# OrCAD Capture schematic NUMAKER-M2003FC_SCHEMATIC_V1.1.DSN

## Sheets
1 Nu-Link2-Me (TypeC): size A3; title: Nu-Link2-Me; rev: 1.0; company: CMHuang; note: Nu-Link2-Me
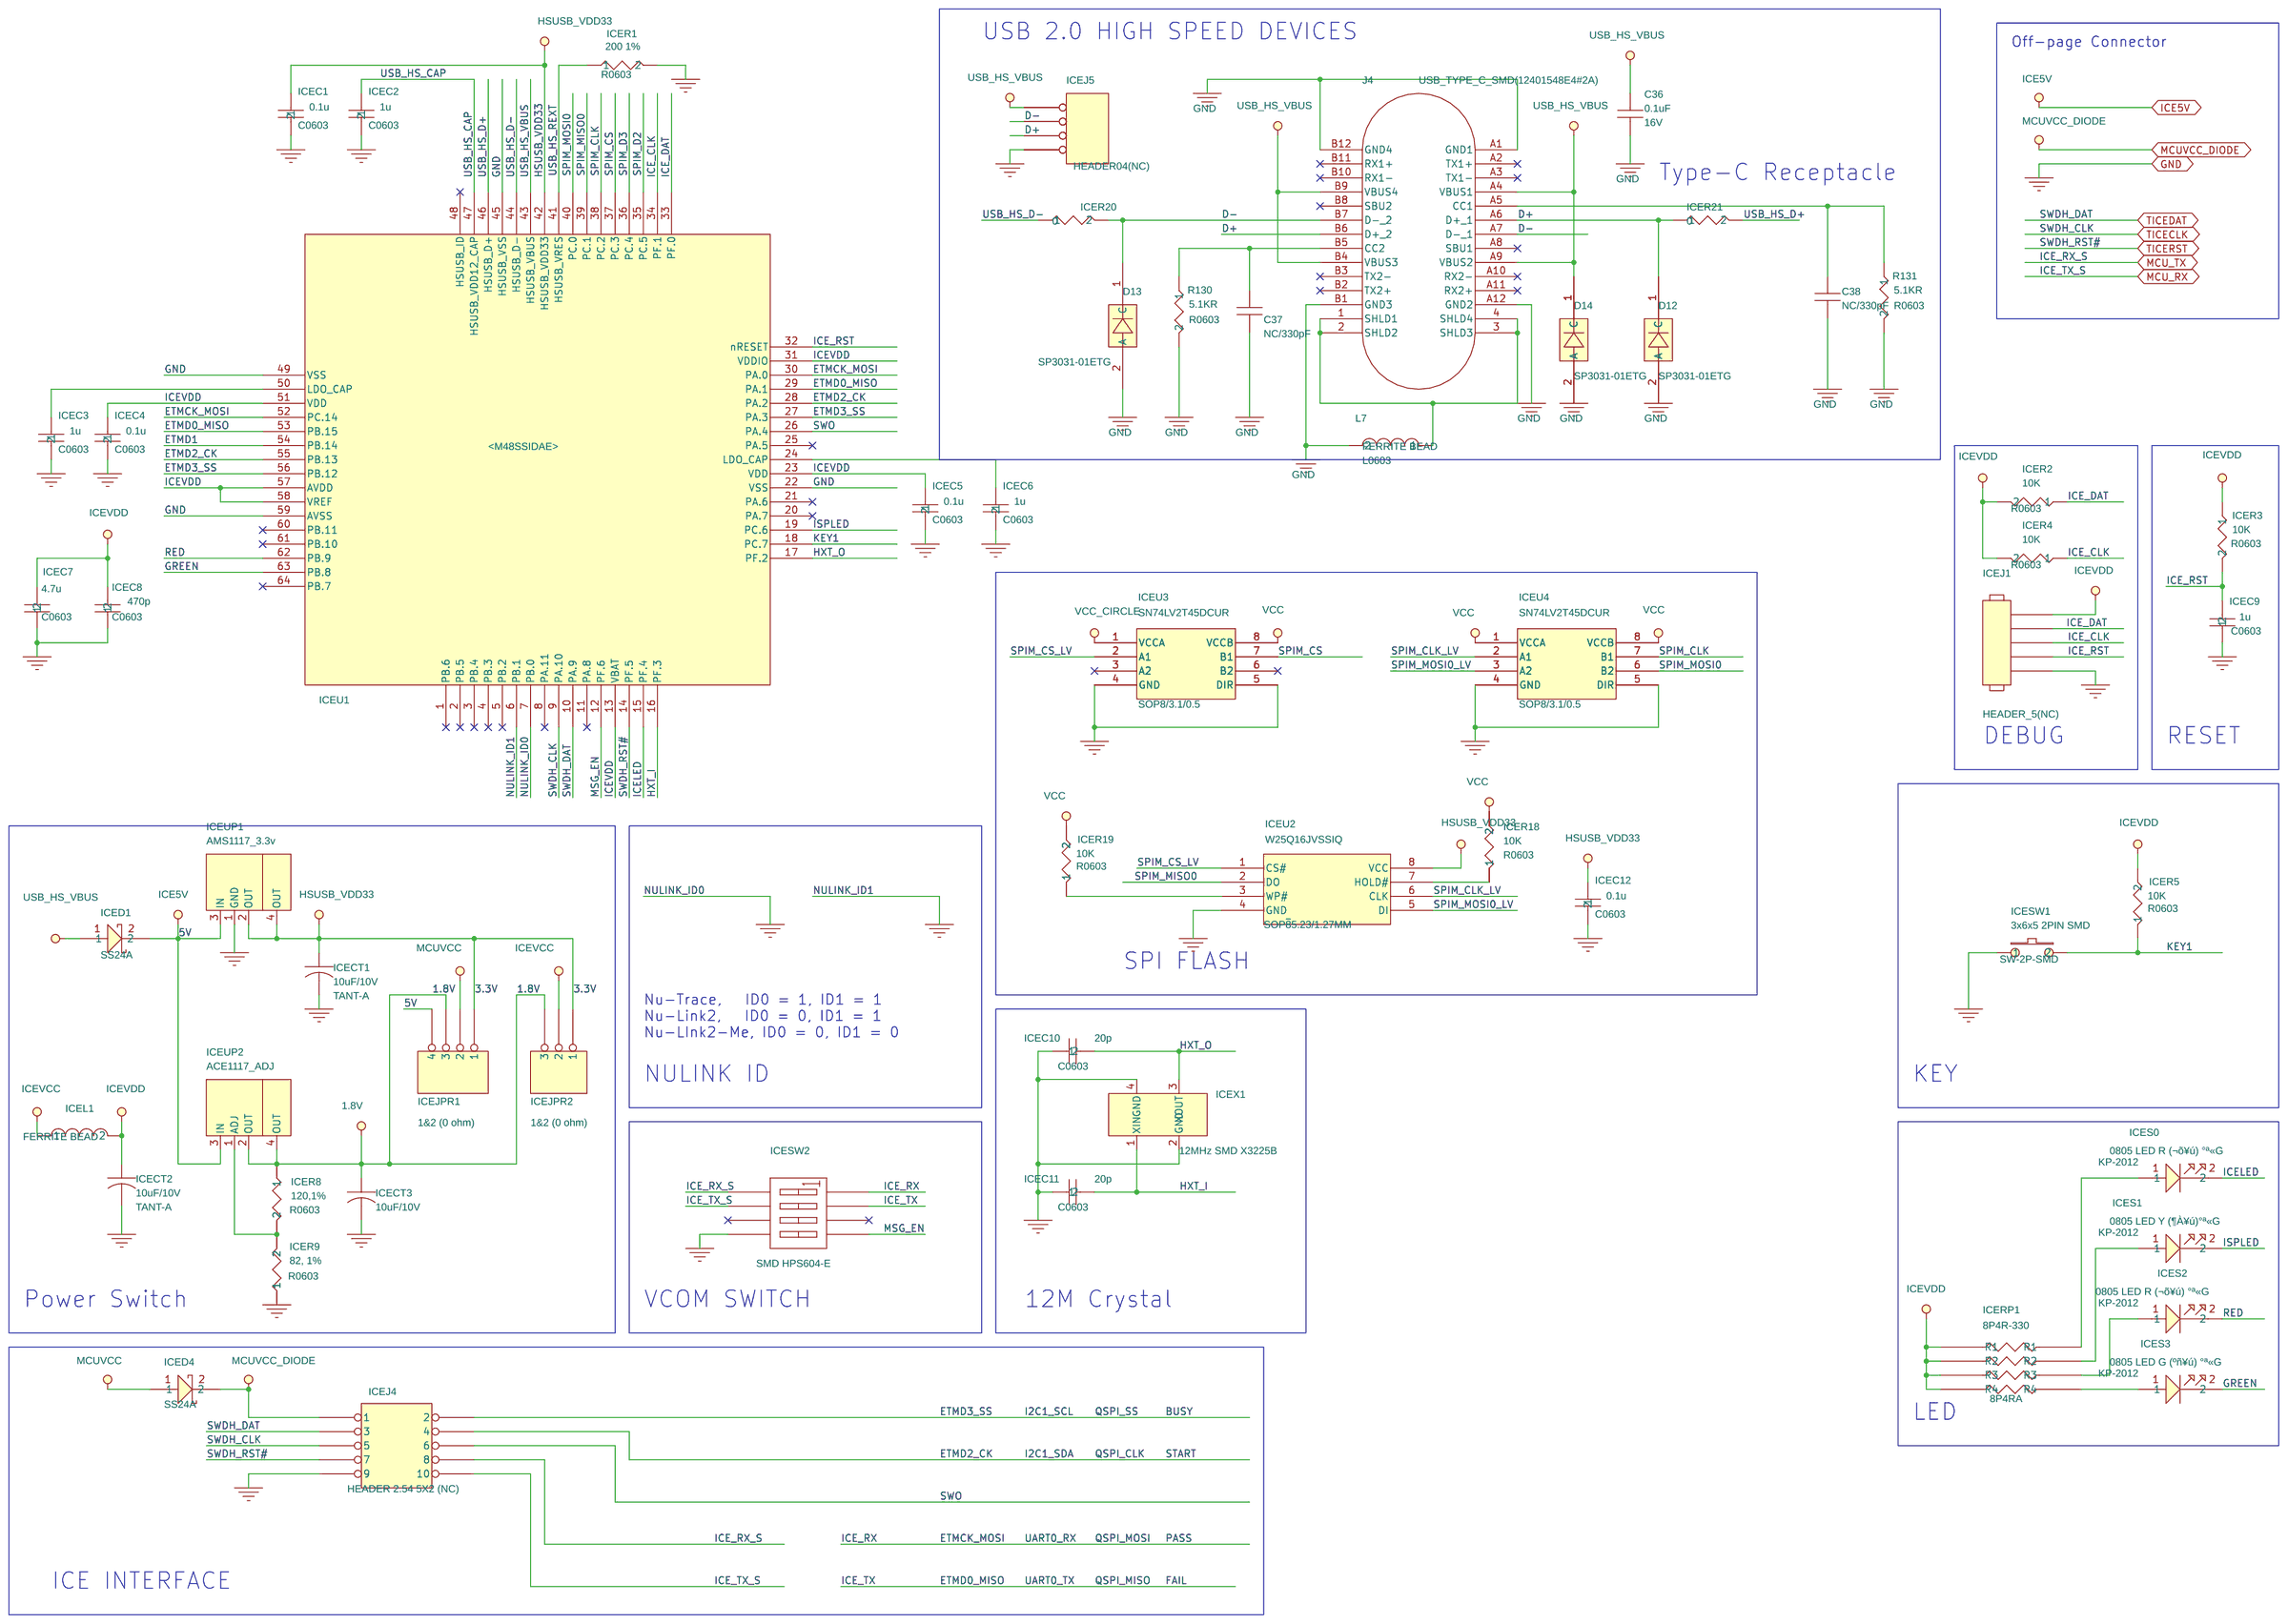
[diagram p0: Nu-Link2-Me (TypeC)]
2 M2003FC1AE: size Custom; title: M2003FC1AE; rev: v1.1; note: NuMaker-M2003FC
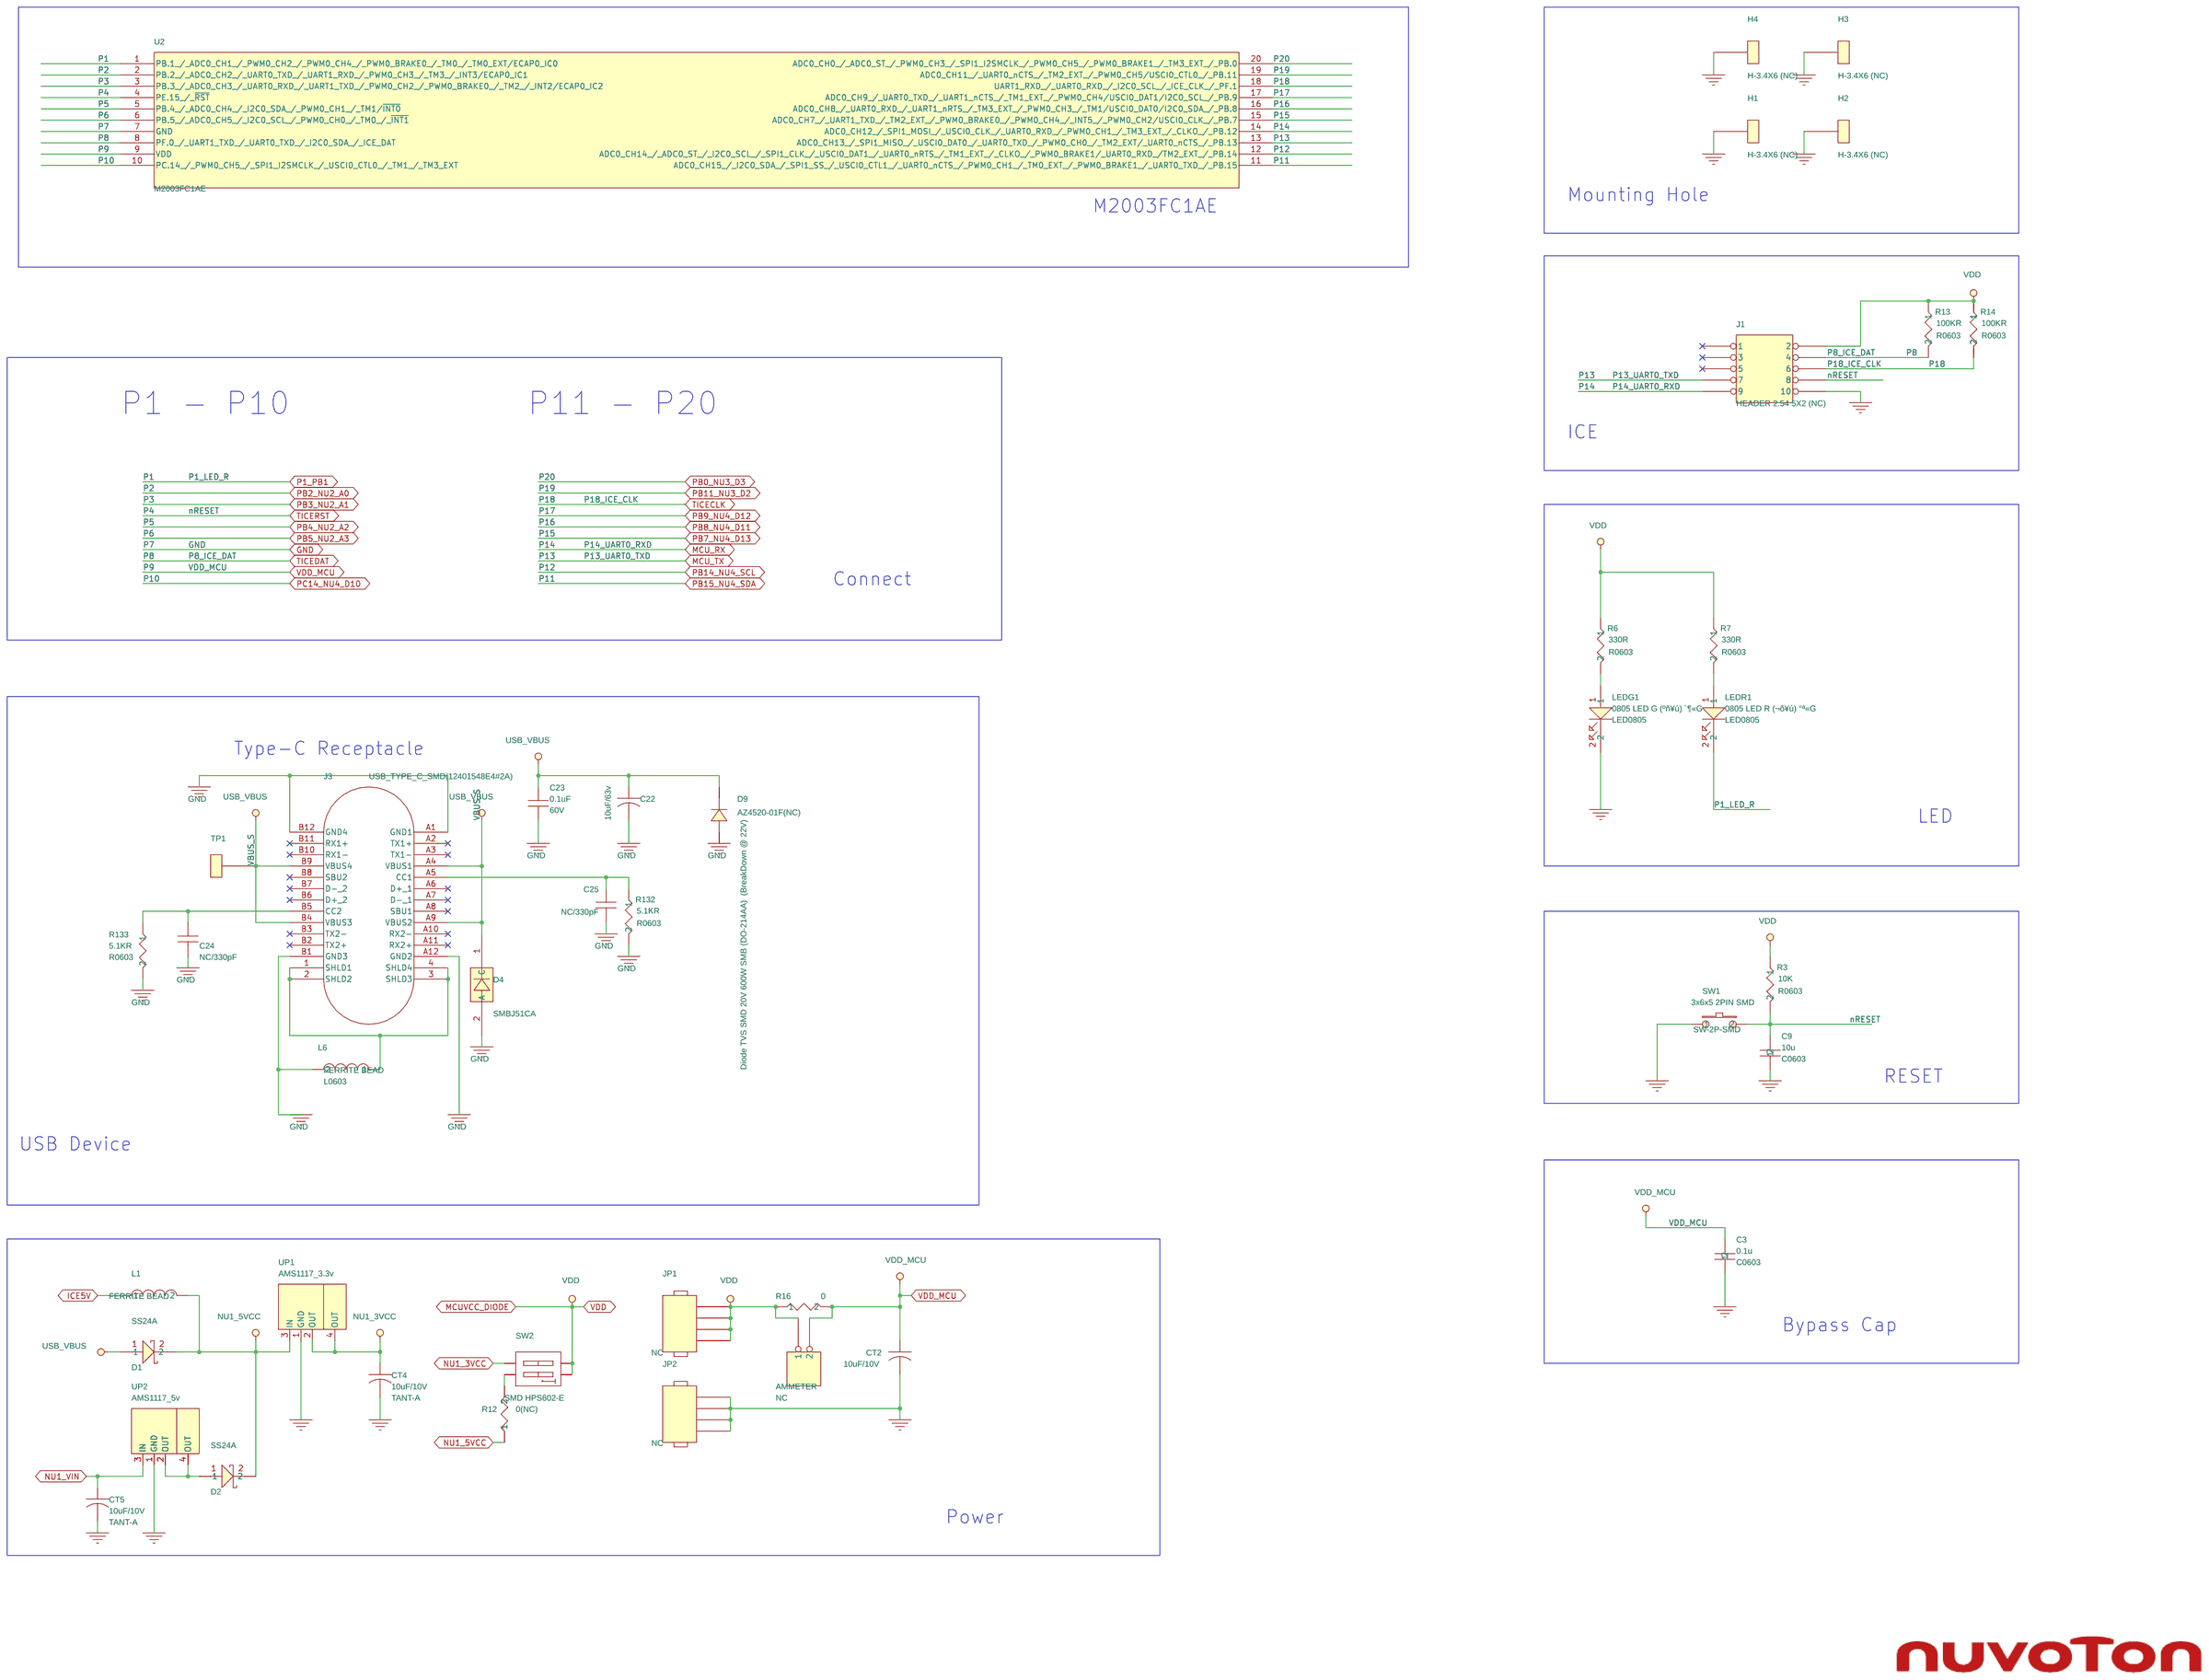
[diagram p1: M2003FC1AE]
3 Ext. Connector: size Custom; title: Ext. Connector; rev: v1.1; note: NuMaker-M2003FC
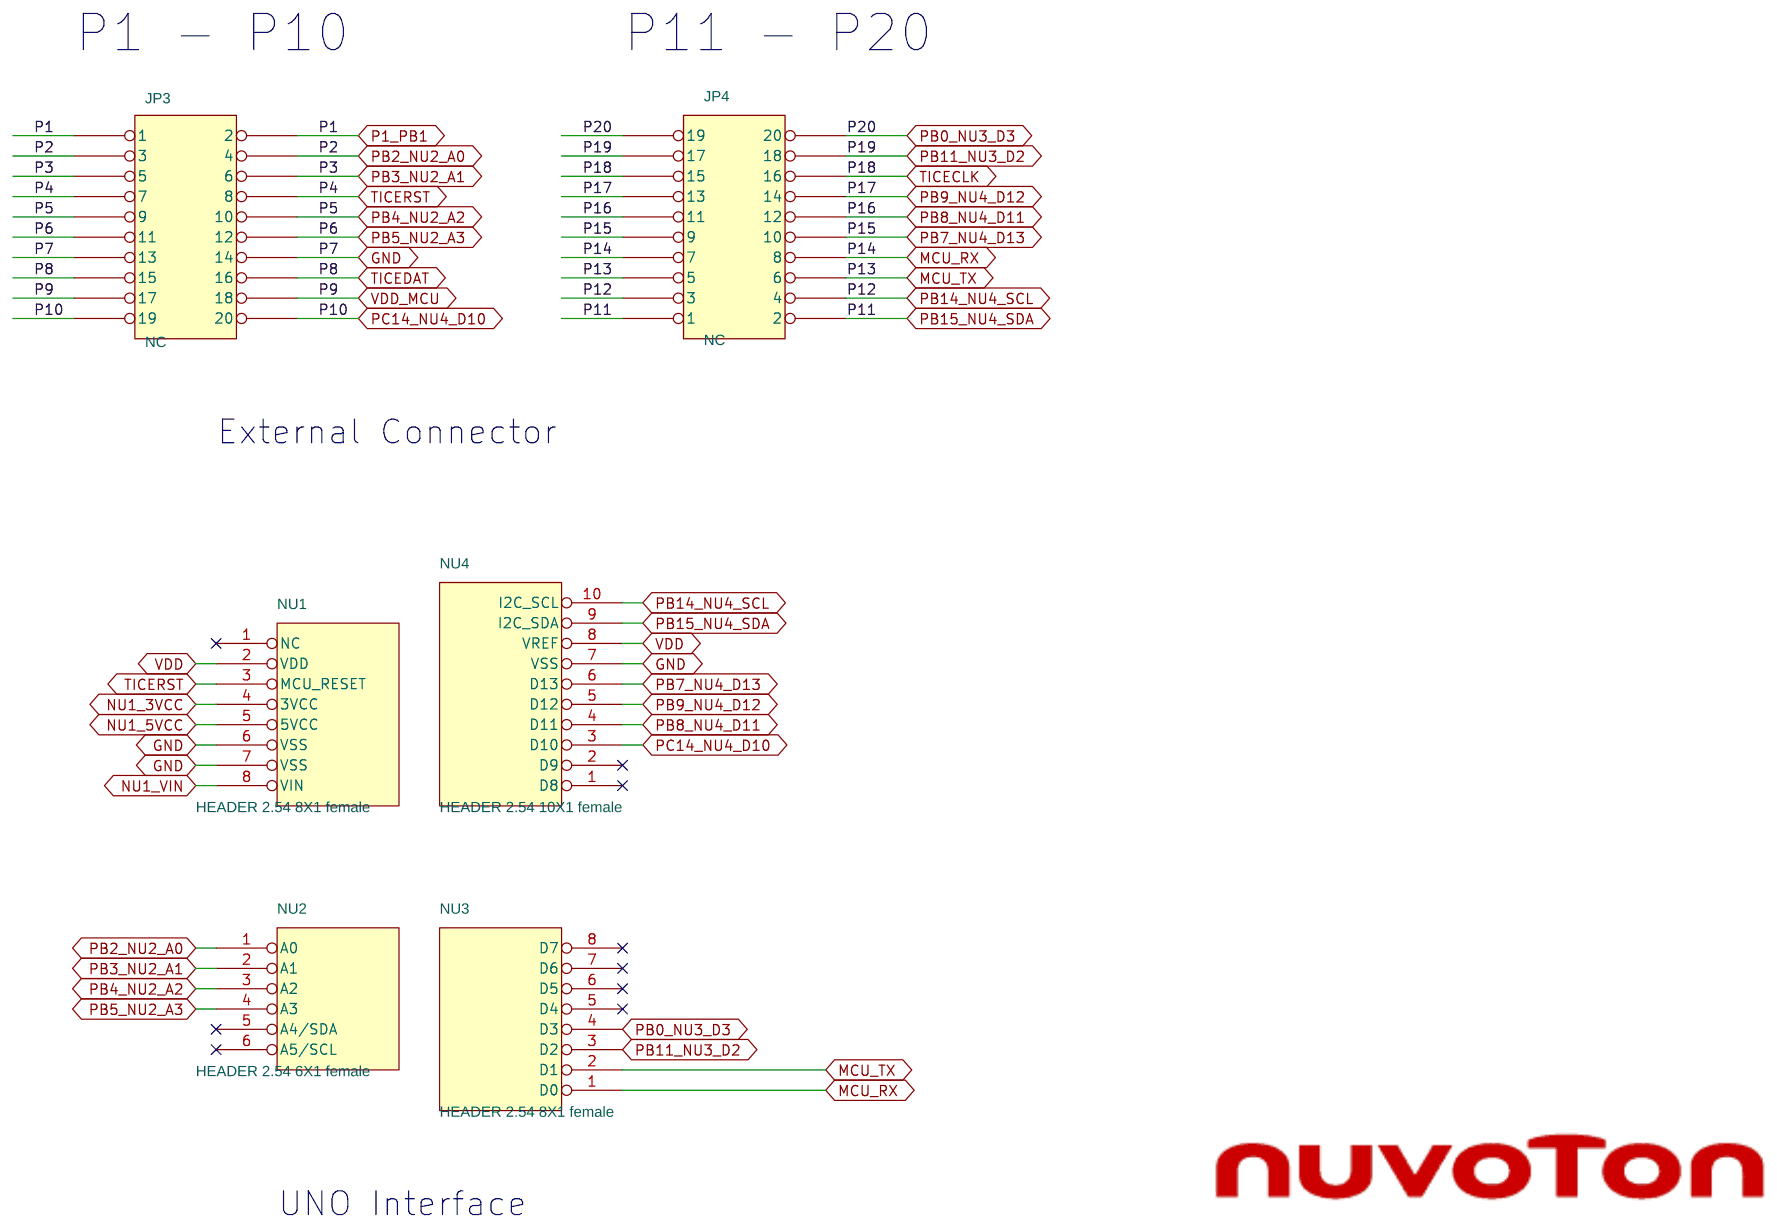
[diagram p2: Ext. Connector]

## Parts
sheet Ext. Connector
JP3  NC  [HEADER10x2]
JP4  NC  [HEADER10x2]
NU1  HEADER 2.54 8X1 female  [SIP-8P]
NU2  HEADER 2.54 6X1 female  [SIP-6P]
NU3  HEADER 2.54 8X1 female  [SIP-8P]
NU4  HEADER 2.54 10X1 female  [SIP-10P]
sheet M2003FC1AE
AMMETER  NC  [HEADER2X1]
C3  0.1u  [C0603]
C9  10u  [C0603]
C22  10uF/63v  [CES/6.3D/P]
C23  0.1uF  [C0603]
C24  NC/330pF  [C0603]
C25  NC/330pF  [C0603]
CT2  10uF/10V  [TANT-A]
CT4  10uF/10V  [TANT-A]
CT5  10uF/10V  [TANT-A]
D1  SS24A  [RB060L]
D2  SS24A  [RB060L]
D4  SMBJ51CA  [DO-214AA]
D9  AZ4520-01F(NC)  [DO-214AA/SMB]
H1  H-3.4X6 (NC)  [H-3.4X6]
H2  H-3.4X6 (NC)  [H-3.4X6]
H3  H-3.4X6 (NC)  [H-3.4X6]
H4  H-3.4X6 (NC)  [H-3.4X6]
J1  HEADER 2.54 5X2 (NC)  [HEADER5X2]
J3  USB_TYPE_C_SMD(12401548E4#2A)  [400981]
JP1  NC  [header1x4]
JP2  NC  [header1x4]
L1  FERRITE BEAD  [L0603]
L6  FERRITE BEAD  [L0603]
LEDG1  0805 LED G (ºñ¥ú) ´¶«G  [LED0805]
LEDR1  0805 LED R (¬õ¥ú) °ª«G  [LED0805]
R3  10K  [R0603]
R6  330R  [R0603]
R7  330R  [R0603]
R12  0(NC)  [R0603]
R13  100KR  [R0603]
R14  100KR  [R0603]
R16  0  [R0603]
R132  5.1KR  [R0603]
R133  5.1KR  [R0603]
SW1  3x6x5 2PIN SMD  [SW-2P-SMD]
SW2  SMD HPS602-E  [SW1X2]
TP1  TEST_POINT
U2  M2003FC1AE  [TSSOP20]
UP1  AMS1117_3.3v  [SOT-223-1]
UP2  AMS1117_5v  [SOT-223-1]
sheet Nu-Link2-Me (TypeC)
C36  0.1uF  [C0603]
C37  NC/330pF  [C0603]
C38  NC/330pF  [C0603]
D12  SP3031-01ETG  [SOD882]
D13  SP3031-01ETG  [SOD882]
D14  SP3031-01ETG  [SOD882]
ICEC1  0.1u  [C0603]
ICEC2  1u  [C0603]
ICEC3  1u  [C0603]
ICEC4  0.1u  [C0603]
ICEC5  0.1u  [C0603]
ICEC6  1u  [C0603]
ICEC7  4.7u  [C0603]
ICEC8  470p  [C0603]
ICEC9  1u  [C0603]
ICEC10  20p  [C0603]
ICEC11  20p  [C0603]
ICEC12  0.1u  [C0603]
ICECT1  10uF/10V  [TANT-A]
ICECT2  10uF/10V  [TANT-A]
ICECT3  10uF/10V  [TANT-A]
ICED1  SS24A  [RB060L]
ICED4  SS24A  [RB060L]
ICEJ1  HEADER_5(NC)  [HEADER5X1]
ICEJ4  HEADER 2.54 5X2 (NC)  [HEADER5X2]
ICEJ5  HEADER04(NC)  [HEADER04]
ICEJPR1  1&2 (0 ohm)  [R0603X3]
ICEJPR2  1&2 (0 ohm)  [R0603X2]
ICEL1  FERRITE BEAD  [L0603]
ICER1  200 1%  [R0603]
ICER2  10K  [R0603]
ICER3  10K  [R0603]
ICER4  10K  [R0603]
ICER5  10K  [R0603]
ICER8  120,1%  [R0603]
ICER9  82, 1%  [R0603]
ICER18  10K  [R0603]
ICER19  10K  [R0603]
ICER20  0  [R0603]
ICER21  0  [R0603]
ICERP1  8P4R-330  [8P4RA]
ICES0  0805 LED R (¬õ¥ú) °ª«G  [KP-2012]
ICES1  0805 LED Y (¶À¥ú)°ª«G  [KP-2012]
ICES2  0805 LED R (¬õ¥ú) °ª«G  [KP-2012]
ICES3  0805 LED G (ºñ¥ú) °ª«G  [KP-2012]
ICESW1  3x6x5 2PIN SMD  [SW-2P-SMD]
ICESW2  SMD HPS604-E  [SW1X4]
ICEU1  M48SSIDAE  [LQFP64_7x7_M48SSIDAE]
ICEU2  W25Q16JVSSIQ  [SOP8\5.23/1.27MM]
ICEU3  SN74LV2T45DCUR  [SOP8/3.1/0.5]
ICEU4  SN74LV2T45DCUR  [SOP8/3.1/0.5]
ICEUP1  AMS1117_3.3v  [SOT-223-1]
ICEUP2  ACE1117_ADJ  [SOT-223-1]
ICEX1  12MHz SMD X3225B  [CRYSTAL_SMD]
J4  USB_TYPE_C_SMD(12401548E4#2A)  [400981]
L7  FERRITE BEAD  [L0603]
R130  5.1KR  [R0603]
R131  5.1KR  [R0603]

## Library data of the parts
JP3 = HEADER_10X2
JP4 = HEADER_10X2_1
NU1 = POWER_CONNECT_0
NU2 = ADC_CONNECT_0
NU3 = PWM0_CONNECT_0
NU4 = PWM1_CONNECT_1
AMMETER = HEADER_2
C3 ICEC4 = CAP-C: Package: 0603; element_no: C0004
C9 = CAP-C_1: Package: 0603; element_no: C0006
C22 CT2 CT4 CT5 ICECT1-ICECT3 = C_10uF_10V
C23 = CAPACITOR_NP: CAP CER X7R SMD 0.1uF 10% 50V 0603; Mount: M; Part Number: 880600286; Part Type: Capacitor\Ceramic; Raing/Power: 60V; Tolerance: 10%
C24 C25 C37 C38 = CAPACITOR_NP: CAP CER NPO SMD 330pF 5% 50V 0603; Mount: M; Part Number: 880600252; Part Type: Capacitor\Ceramic; Raing/Power: 50V; Tolerance: 5%
D1 ICED4 = D_SS24A_1
D2 ICED1 = D_SS24A
D4 = Schottky_Barrier_Diode_0: Diode SMD Schottky Barrier 30V; Mount: M; Part Number: 880900908
D9 = DIODE21: Diode TVS SMD 20V 600W SMB (DO-214AA)  (BreakDown @ 22V); Mount: M; Part Number: 880900866; Part Type: Diode
H1-H4 TP1 = TEST_POINT
ICEJ4 J1 = HEADER_5X2
J3 J4 = USB_TYPE_C_2: CON USB 3.0 Type C receptical SMD & TH; Mount: M; Part Number: 880400981; Part Type: Connector
JP1 JP2 = HEADER_4
ICEL1 L1 = FERRITE_BEAD_1
L6 L7 = FERRITE_BEAD
LEDG1 = LED_0_1: Package: KP-2012; Vendor: Kingbright
LEDR1 = LED_0: Package: KP-2012; Vendor: Kingbright
ICER5 R3 = R_0_2: Package: 0603
ICER2 R6 = R_0_5: Package: 0603
ICER8 R7 = R_0: Package: 0603
R12 = R_0_6
ICER18 R13 = R_0_4: Package: 0603
ICER1 R14 = R_0_7: Package: 0603
R16 = R_0_8
ICER4 R132 = R_0_3: Package: 0603
ICER3 R133 = R_0_1: Package: 0603
ICESW1 SW1 = SW_PUSHBUTTON_0
SW2 = SW_DIP-4_2
U2 = SA8191_LQFP_48L_2
ICEUP1 UP1 UP2 = TO-247_Regulator_10
C36 = CAPACITOR_NP: CAP CER X7R SMD 0.1uF 10% 50V 0603; Mount: M; Part Number: 880600286; Part Type: Capacitor\Ceramic; Raing/Power: 16V; Tolerance: 10%
D12-D14 = Schottky_Barrier_Diode_1: Diode SMD Schottky Barrier 30V; Mount: M; Part Number: 880900908
ICEC1 = CAP-C_10: Package: 0603; element_no: C0004
ICEC2 = CAP-C_9: Package: 0603; element_no: C0006
ICEC3 = CAP-C_7: Package: 0603; element_no: C0006
ICEC5 = CAP-C_2: Package: 0603; element_no: C0004
ICEC6 = CAP-C_5: Package: 0603; element_no: C0006
ICEC7 = CAP-C_3: Package: 0603
ICEC8 = CAP-C_8: Package: 0603
ICEC9 = CAP-C_6: Package: 0603; element_no: C0006
ICEC10 = CAP-C_11: Package: 0603
ICEC11 = CAP-C_4: Package: 0603
ICEC12 = CAP-C_1: Package: 0603; element_no: C0004
ICEJ1 = HEADER_5_v2
ICEJ5 = HEADER_4_v2
ICEJPR1 = HEADER_3_0
ICEJPR2 = HEADER_3
ICER9 = R_0_8: Package: 0603
ICER19 = R_0_10: Package: 0603
ICER20 = R_33
ICER21 = R_33_1
ICERP1 = R-PACK8_0
ICES0 = LED_0_2: Vendor: Kingbright
ICES1 = LED_0_3: Vendor: Kingbright
ICES2 = LED_0_1: Vendor: Kingbright
ICES3 = LED_0: Vendor: Kingbright
ICESW2 = SW_DIP-4_SM
ICEU1 = M487SIDAE_0: M487SIDAE: <M48SSIDAE>
ICEU2 = W25P10_20_40_SOIC_0: Package: SOP8; Vendor: WINBOND
ICEU3 ICEU4 = SN74LV2T45
ICEUP2 = TO-247_Regulator_0
ICEX1 = Crystal_SMD_1
R130 = R_0_6: Package: 0603
R131 = R_0_9: Package: 0603

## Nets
1.8V: ICECT3.1 ICEJPR1.3 ICEJPR2.3 ICER8.1 ICEUP2.2(OUT) ICEUP2.4(OUT)
3.3V: ICEC1.1 ICEC12.1 ICECT1.1 ICEJPR1.1 ICEJPR2.1 ICER18.2 ICER19.2 ICEU1.42(HSUSB_VDD33) ICEU2.8(VCC) ICEU3.1(VCCA) ICEU4.1(VCCA) ICEUP1.2(OUT) ICEUP1.4(OUT)
GND: C3.1 C9.1 C22.2 C23.2 C24.2 C25.2 C36.2 C37.2 C38.2 CT2.2 CT4.2 CT5.2 D4.2(A) D9.2(A) D12.2(A) D13.2(A) D14.2(A) H1.1 H2.1 H3.1 H4.1 ICEC1.2 ICEC2.2 ICEC3.2 ICEC4.2 ICEC5.2 ICEC6.2 ICEC7.1 ICEC8.1 ICEC9.1 ICEC10.1 ICEC11.1 ICEC12.2 ICECT1.2 ICECT2.2 ICECT3.2 ICEJ1.5 ICEJ4.9 ICEJ5.4 ICER1.2 ICER9.1 ICESW1.1 ICESW2.4(A4) ICEU1.6(PB.1) ICEU1.7(PB.0) ICEU1.22(VSS) ICEU1.45(HSUSB_VSS) ICEU1.49(VSS) ICEU1.59(AVSS) ICEU2.4(GND) ICEU3.4(GND) ICEU3.5(DIR) ICEU4.4(GND) ICEU4.5(DIR) ICEUP1.1(GND) ICEX1.2(GND) ICEX1.4(GND) J1.10 J3.A1(GND1) J3.A12(GND2) J3.B1(GND3) J3.B12(GND4) J4.A1(GND1) J4.A12(GND2) J4.B1(GND3) J4.B12(GND4) JP2.1 JP2.2 JP2.3 JP2.4 JP3.13 JP3.14 L6.2 L7.2 LEDG1.2 NU1.6(VSS) NU1.7(VSS) NU4.7(VSS) R130.2 R131.2 R132.2 R133.2 SW1.1 U2.7(GND) UP1.1(GND) UP2.1(GND)
VDD: AMMETER.1 ICED4.2 ICEJ4.1 J1.2 JP1.1 JP1.2 JP1.3 JP1.4 NU1.2(VDD) NU4.8(VREF) R3.1 R6.1 R7.1 R13.1 R14.1 R16.1 SW2.3(B1) SW2.4(B2)
VDD_MCU: AMMETER.2 C3.2 CT2.1 JP3.17 JP3.18 R16.2 U2.9(VDD)
BUSY: ICEJ4.2 ICEU1.27(PA.3) ICEU1.56(PB.12)
D+: D12.1(C) ICEJ5.3 ICER21.1 J4.A6(D+_1) J4.B6(D+_2)
D-: D13.1(C) ICEJ5.2 ICER20.2 J4.A7(D-_1) J4.B7(D-_2)
ETMD1: ICEU1.54(PB.14)
ETMD2_CK: ICEJ4.4 ICEU1.28(PA.2) ICEU1.55(PB.13)
GREEN: ICES3.2 ICEU1.63(PB.8)
HXT_I: ICEC11.2 ICEU1.16(PF.3) ICEX1.1(XIN)
HXT_O: ICEC10.2 ICEU1.17(PF.2) ICEX1.3(XOUT)
ICE5V: ICED1.2 ICEJPR1.4 ICEUP1.3(IN) ICEUP2.3(IN) L1.1
ICE_CLK: ICEJ1.3 ICER4.1 ICEU1.34(PF.1)
ICE_DAT: ICEJ1.2 ICER2.1 ICEU1.33(PF.0)
ICE_RST: ICEC9.2 ICEJ1.4 ICER3.2 ICEU1.32(nRESET)
ICE_RX: ICESW2.8(B1) ICEU1.30(PA.0) ICEU1.52(PC.14)
ICE_TX: ICESW2.7(B2) ICEU1.29(PA.1) ICEU1.53(PB.15)
ICELED: ICES0.2 ICEU1.15(PF.4)
ICEVCC: ICEJPR2.2 ICEL1.1
ICEVDD: ICEC4.1 ICEC5.1 ICEC7.2 ICEC8.2 ICECT2.1 ICEJ1.1 ICEL1.2 ICER2.2 ICER3.1 ICER4.2 ICER5.2 ICERP1.1(R1) ICERP1.3(R2) ICERP1.5(R3) ICERP1.7(R4) ICEU1.13(VBAT) ICEU1.23(VDD) ICEU1.31(VDDIO) ICEU1.51(VDD) ICEU1.57(AVDD) ICEU1.58(VREF) ICEU3.8(VCCB) ICEU4.8(VCCB)
ISPLED: ICES1.2 ICEU1.19(PC.6)
KEY1: ICER5.1 ICESW1.2 ICEU1.18(PC.7)
MCU_RX: ICEJ4.10 ICESW2.2(A2) J1.9 JP4.7 JP4.8 NU3.1(D0) U2.14(ADC0_CH12_/_SPI1_MOSI_/_USCI0_CLK_/_UART0_RXD_/_PWM0_CH1_/_TM3_EXT_/_CLKO_/_PB.12)
MCU_TX: ICEJ4.8 ICESW2.1(A1) J1.7 JP4.5 JP4.6 NU3.2(D1) U2.13(ADC0_CH13_/_SPI1_MISO_/_USCI0_DAT0_/_UART0_TXD_/_PWM0_CH0_/_TM2_EXT/_UART0_nCTS_/_PB.13)
MCUVCC: ICED4.1 ICEJPR1.2
MSG_EN: ICESW2.5(B4) ICEU1.12(PF.6)
NU1_3VCC: CT4.1 NU1.4(3VCC) SW2.2(A2) UP1.2(OUT) UP1.4(OUT)
NU1_5VCC: D1.2 D2.2 L1.2 NU1.5(5VCC) R12.1 UP1.3(IN)
NU1_VIN: CT5.1 NU1.8(VIN) UP2.3(IN)
P1_PB1: JP3.1 JP3.2 LEDR1.2 U2.1(PB.1_/_ADC0_CH1_/_PWM0_CH2_/_PWM0_CH4_/_PWM0_BRAKE0_/_TM0_/_TM0_EXT/ECAP0_IC0)
PB0_NU3_D3: JP4.19 JP4.20 NU3.4(D3) U2.20(ADC0_CH0_/_ADC0_ST_/_PWM0_CH3_/_SPI1_I2SMCLK_/_PWM0_CH5_/_PWM0_BRAKE1_/_TM3_EXT_/_PB.0)
PB2_NU2_A0: JP3.3 JP3.4 NU2.1(A0) U2.2(PB.2_/_ADC0_CH2_/_UART0_TXD_/_UART1_RXD_/_PWM0_CH3_/_TM3_/_INT3/ECAP0_IC1)
PB3_NU2_A1: JP3.5 JP3.6 NU2.2(A1) U2.3(PB.3_/_ADC0_CH3_/_UART0_RXD_/_UART1_TXD_/_PWM0_CH2_/_PWM0_BRAKE0_/_TM2_/_INT2/ECAP0_IC2)
PB4_NU2_A2: JP3.9 JP3.10 NU2.3(A2) U2.5(PB.4_/_ADC0_CH4_/_I2C0_SDA_/_PWM0_CH1_/_TM1/~{INT0})
PB5_NU2_A3: JP3.11 JP3.12 NU2.4(A3) U2.6(PB.5_/_ADC0_CH5_/_I2C0_SCL_/_PWM0_CH0_/_TM0_/_~{INT1})
PB7_NU4_D13: JP4.9 JP4.10 NU4.6(D13) U2.15(ADC0_CH7_/_UART1_TXD_/_TM2_EXT_/_PWM0_BRAKE0_/_PWM0_CH4_/_INT5_/_PWM0_CH2/USCI0_CLK_/_PB.7)
PB8_NU4_D11: JP4.11 JP4.12 NU4.4(D11) U2.16(ADC0_CH8_/_UART0_RXD_/_UART1_nRTS_/_TM3_EXT_/_PWM0_CH3_/_TM1/USCI0_DAT0/I2C0_SDA_/_PB.8)
PB9_NU4_D12: JP4.13 JP4.14 NU4.5(D12) U2.17(ADC0_CH9_/_UART0_TXD_/_UART1_nCTS_/_TM1_EXT_/_PWM0_CH4/USCI0_DAT1/I2C0_SCL_/_PB.9)
PB11_NU3_D2: JP4.17 JP4.18 NU3.3(D2) U2.19(ADC0_CH11_/_UART0_nCTS_/_TM2_EXT_/_PWM0_CH5/USCI0_CTL0_/_PB.11)
PB14_NU4_SCL: JP4.3 JP4.4 NU4.10(I2C_SCL) U2.12(ADC0_CH14_/_ADC0_ST_/_I2C0_SCL_/_SPI1_CLK_/_USCI0_DAT1_/_UART0_nRTS_/_TM1_EXT_/_CLKO_/_PWM0_BRAKE1/_UART0_RXD_/TM2_EXT_/_PB.14)
PB15_NU4_SDA: JP4.1 JP4.2 NU4.9(I2C_SDA) U2.11(ADC0_CH15_/_I2C0_SDA_/_SPI1_SS_/_USCI0_CTL1_/_UART0_nCTS_/_PWM0_CH1_/_TM0_EXT_/_PWM0_BRAKE1_/_UART0_TXD_/_PB.15)
PC14_NU4_D10: JP3.19 JP3.20 NU4.3(D10) U2.10(PC.14_/_PWM0_CH5_/_SPI1_I2SMCLK_/_USCI0_CTL0_/_TM1_/_TM3_EXT)
RED: ICES2.2 ICEU1.62(PB.9)
SPIM_CLK: ICEU1.38(PC.2) ICEU4.7(B1)
SPIM_CLK_LV: ICEU2.6(CLK) ICEU4.2(A1)
SPIM_CS: ICEU1.37(PC.3) ICEU3.7(B1)
SPIM_CS_LV: ICEU2.1(CS#) ICEU3.2(A1)
SPIM_D2: ICEU1.35(PC.5)
SPIM_D3: ICEU1.36(PC.4)
SPIM_MISO0: ICEU1.39(PC.1) ICEU2.2(DO)
SPIM_MOSI0: ICEU1.40(PC.0) ICEU4.6(B2)
SPIM_MOSI0_LV: ICEU2.5(DI) ICEU4.3(A2)
SWO: ICEJ4.6 ICEU1.26(PA.4)
TICECLK: ICEJ4.5 ICEU1.9(PA.10) J1.6 JP4.15 JP4.16 R14.2 U2.18(UART1_RXD_/_UART0_RXD_/_I2C0_SCL_/_ICE_CLK_/_PF.1)
TICEDAT: ICEJ4.3 ICEU1.10(PA.9) J1.4 JP3.15 JP3.16 R13.2 U2.8(PF.0_/_UART1_TXD_/_UART0_TXD_/_I2C0_SDA_/_ICE_DAT)
TICERST: C9.2 ICEJ4.7 ICEU1.14(PF.5) J1.8 JP3.7 JP3.8 NU1.3(MCU_RESET) R3.2 SW1.2 U2.4(PE.15_/_~{RST})
USB_HS_CAP: ICEC2.1 ICEU1.47(HSUSB_VDD12_CAP)
USB_HS_D+: ICER21.2 ICEU1.46(HSUSB_D+)
USB_HS_D-: ICER20.1 ICEU1.44(HSUSB_D-)
USB_HS_REXT: ICER1.1 ICEU1.41(HSUSB_VRES)
USB_HS_VBUS: C36.1 D14.1(C) ICED1.1 ICEJ5.1 ICEU1.43(HSUSB_VBUS) J4.A4(VBUS1) J4.A9(VBUS2) J4.B4(VBUS3) J4.B9(VBUS4)
USB_VBUS: C22.1 C23.1 D1.1 D4.1(C) D9.1(K) J3.A4(VBUS1) J3.A9(VBUS2) J3.B4(VBUS3) J3.B9(VBUS4) TP1.1
N16825237: LEDG1.1 R6.2
N16825240: LEDR1.1 R7.2
N16840819: ICEC6.1 ICEU1.24(LDO_CAP)
N16840960: ICEC3.1 ICEU1.50(LDO_CAP)
N17019924: ICER8.2 ICER9.2 ICEUP2.1(ADJ)
N17029977: ICERP1.8(R4) ICES3.1
N17029979: ICERP1.6(R3) ICES2.1
N17030004: ICERP1.4(R2) ICES1.1
N17030010: ICERP1.2(R1) ICES0.1
N17125028: R12.2 SW2.1(A1)
N17155328: ICER18.1 ICEU2.7(HOLD#)
N17155343: ICER19.1 ICEU2.3(WP#)
N17167442: D2.1 UP2.2(OUT) UP2.4(OUT)
N17285540: C25.1 J3.A5(CC1) R132.1
N17285578: C24.1 J3.B5(CC2) R133.1
N17285609: J3.1(SHLD1) J3.2(SHLD2) J3.3(SHLD3) J3.4(SHLD4) L6.1
N17357255: C38.1 J4.A5(CC1) R131.1
N17357296: C37.1 J4.B5(CC2) R130.1
N17357342: J4.1(SHLD1) J4.2(SHLD2) J4.3(SHLD3) J4.4(SHLD4) L7.1

Not connected (* = marked no-connect by the designer): ICESW2 3(A3)* 6(B3)*; ICEU1 1(PB.6)* 2(PB.5)* 3(PB.4)* 4(PB.3)* 5(PB.2)* 8(PA.11)* 11(PA.8)* 20(PA.7)* 21(PA.6)* 25(PA.5)* 48(HSUSB_ID)* 60(PB.11)* 61(PB.10)* 64(PB.7)*; ICEU3 3(A2)* 6(B2)*; J1 1* 3* 5*; J3 A2(TX1+)* A3(TX1-)* A6(D+_1)* A7(D-_1)* A8(SBU1)* A10(RX2-)* A11(RX2+)* B2(TX2+)* B3(TX2-)* B6(D+_2)* B7(D-_2)* B8(SBU2)* B10(RX1-)* B11(RX1+)*; J4 A2(TX1+)* A3(TX1-)* A8(SBU1)* A10(RX2-)* A11(RX2+)* B2(TX2+)* B3(TX2-)* B8(SBU2)* B10(RX1-)* B11(RX1+)*; NU1 1(NC)*; NU2 5(A4/SDA)* 6(A5/SCL)*; NU3 5(D4)* 6(D5)* 7(D6)* 8(D7)*; NU4 1(D8)* 2(D9)*

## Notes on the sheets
sheet 1
- USB 2.0 HIGH SPEED DEVICES
- Off-page Connector
- Type-C Receptacle
- DEBUG
- RESET
- SPI FLASH
- Nu-Trace,   ID0 = 1, ID1 = 1
  Nu-Link2,   ID0 = 0, ID1 = 1
  Nu-LInk2-Me, ID0 = 0, ID1 = 0
- NULINK ID
- KEY
- Power Switch
- VCOM SWITCH
- 12M Crystal
- LED
- ICE INTERFACE
sheet 2
- M2003FC1AE
- Mounting Hole
- P1 - P10
- P11 - P20
- ICE
- Connect
- Type-C Receptacle
- LED
- RESET
- USB Device
- Bypass Cap
- Power
sheet 3
- P1 - P10
- P11 - P20
- External Connector
- UNO Interface
